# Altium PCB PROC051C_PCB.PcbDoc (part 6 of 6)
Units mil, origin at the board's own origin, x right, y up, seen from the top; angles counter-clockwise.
Board outline 3304.03 x 2647.77 mil, 6 copper layers (TOP, L2, L3, L4, L5, BOTTOM), stack 55.54 mil thick; 370 components, 273 nets, 1273 pads, 1381 vias.
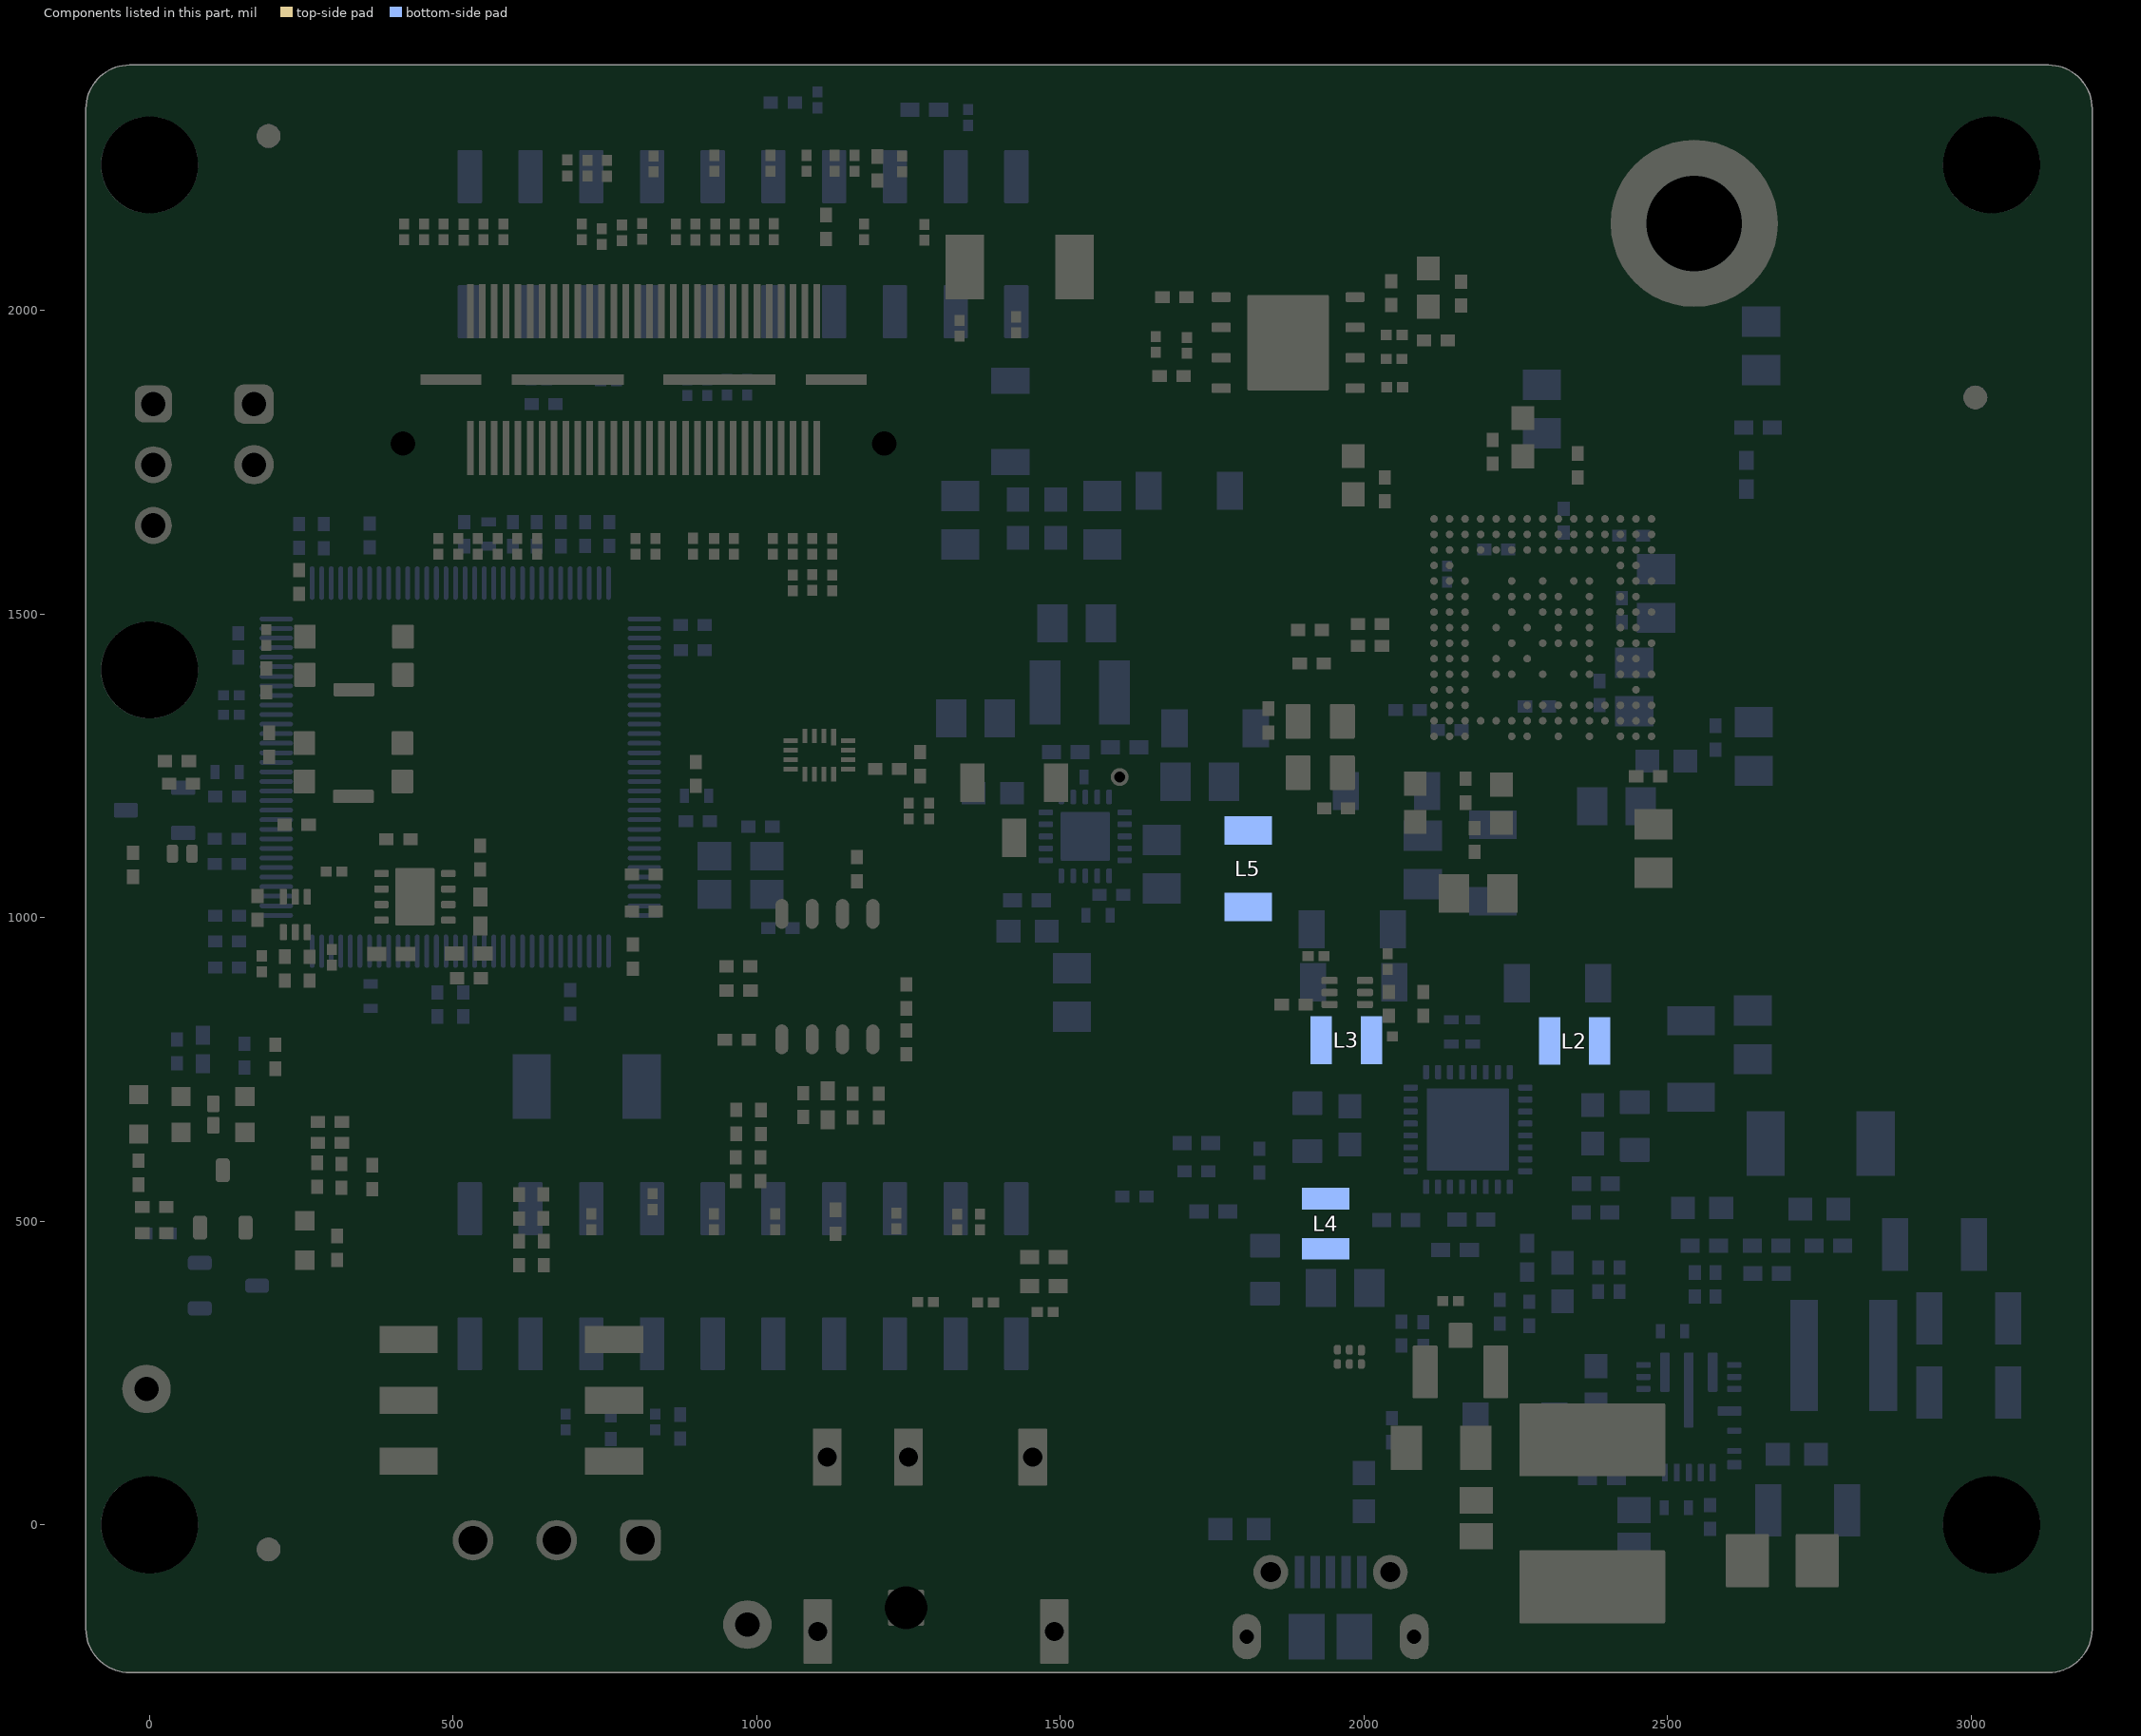
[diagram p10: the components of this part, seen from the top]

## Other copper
TOP:
  pour cut-out: 2104.44,2178.01 2104.44,2191.79 2120.19,2191.79 2143.81,2195.15 2291.6,2195.15 2315.22,2191.79 2330.97,2191.79 2330.97,2178.01 2315.22,2178.01 2291.6,2174.65 2143.81,2174.65 2120.19,2178.01
  pour cut-out: 1627.59,2266.11 1627.59,2279.89 1643.34,2279.89 1666.96,2283.25 2292.4,2283.25 2316.02,2279.89 2331.77,2279.89 2331.77,2266.11 2316.02,2266.11 2292.4,2262.75 1666.96,2262.75 1643.34,2266.11
  pour cut-out: 2361.84,1324.36 2360.61,1330.52 2357.12,1335.75 2351.89,1339.24 2345.73,1340.47 2339.57,1339.24 2334.34,1335.75 2330.85,1330.52 2329.62,1324.36 2330.85,1318.2 2334.34,1312.97 2339.57,1309.48 2345.73,1308.25 2351.89,1309.48 2357.12,1312.97 2360.61,1318.2 2361.84,1324.36
  pour cut-out: 2263.01,1622.77 2263.36,1622.51 2263.68,1622.22 2263.98,1621.9 2264.25,1621.55 2264.49,1621.19 2264.69,1620.8 2264.86,1620.4 2265,1619.99 2265.1,1619.56 2265.16,1619.13 2265.18,1618.69 2265.16,1618.26 2265.11,1617.83 2265.02,1617.4 2264.89,1616.98 2264.73,1616.58 2264.53,1616.19 2264.3,1615.82 2264.04,1615.47 2263.75,1615.15 2263.43,1614.85 2263.08,1614.58 2263.01,1614.52 2262.28,1613.97 2261.6,1613.35 2260.97,1612.68 2260.4,1611.96 2259.9,1611.19 2259.47,1610.38 2259.11,1609.54 2258.83,1608.66 2258.73,1608.31 2258.57,1607.63 2256.3,1605.36 2253.7,1607.97 2253.52,1608.61 2253.24,1609.48 2252.89,1610.33 2252.46,1611.14 2251.97,1611.92 2251.4,1612.64 2250.78,1613.32 2250.1,1613.93 2249.37,1614.49 2249.32,1614.52 2249.32,1614.53 2248.97,1614.79 2248.65,1615.08 2248.35,1615.4 2248.08,1615.74 2247.85,1616.11 2247.64,1616.49 2247.47,1616.89 2247.33,1617.31 2247.24,1617.73 2247.17,1618.16 2247.15,1618.6 2247.16,1619.04 2247.22,1619.47 2247.31,1619.9 2247.43,1620.31 2247.6,1620.72 2247.79,1621.11 2248.03,1621.48 2248.29,1621.82 2248.58,1622.15 2248.9,1622.45 2249.24,1622.72 2249.32,1622.77 2250.05,1623.32 2250.73,1623.94 2251.36,1624.61 2251.93,1625.33 2252.43,1626.1 2252.86,1626.91 2253.22,1627.75 2253.28,1627.91 2253.47,1628.44 2255.63,1630.6 2259.59,1626.65 2259.76,1626.34 2260.24,1625.56 2260.79,1624.82 2261.4,1624.14 2262.07,1623.5 2262.78,1622.93 2263.01,1622.77
  pour cut-out: 2288.6,1622.77 2288.95,1622.51 2289.27,1622.22 2289.57,1621.9 2289.84,1621.55 2290.08,1621.19 2290.28,1620.8 2290.45,1620.4 2290.59,1619.99 2290.69,1619.56 2290.75,1619.13 2290.77,1618.69 2290.75,1618.26 2290.7,1617.83 2290.61,1617.4 2290.48,1616.98 2290.32,1616.58 2290.12,1616.19 2289.89,1615.82 2289.63,1615.47 2289.34,1615.15 2289.02,1614.85 2288.67,1614.58 2288.6,1614.52 2287.87,1613.97 2287.19,1613.35 2286.56,1612.68 2285.99,1611.96 2285.49,1611.19 2285.06,1610.38 2284.7,1609.54 2284.64,1609.38 2284.45,1608.85 2282.29,1606.69 2278.33,1610.64 2278.16,1610.95 2277.68,1611.73 2277.13,1612.47 2276.52,1613.15 2275.85,1613.79 2275.14,1614.36 2274.91,1614.52 2274.91,1614.53 2274.57,1614.79 2274.24,1615.08 2273.94,1615.4 2273.67,1615.74 2273.44,1616.11 2273.23,1616.49 2273.06,1616.89 2272.92,1617.31 2272.82,1617.73 2272.76,1618.16 2272.74,1618.6 2272.75,1619.04 2272.81,1619.47 2272.9,1619.9 2273.02,1620.31 2273.19,1620.72 2273.38,1621.11 2273.62,1621.48 2273.88,1621.82 2274.17,1622.15 2274.49,1622.45 2274.83,1622.72 2274.91,1622.77 2275.64,1623.32 2276.32,1623.94 2276.95,1624.61 2277.52,1625.33 2278.02,1626.1 2278.45,1626.91 2278.81,1627.75 2278.87,1627.91 2279.06,1628.44 2281.22,1630.6 2285.18,1626.65 2285.35,1626.34 2285.83,1625.56 2286.38,1624.82 2286.99,1624.14 2287.66,1623.5 2288.37,1622.93 2288.6,1622.77
  pour cut-out: 2413.02,1324.36 2411.79,1330.52 2408.3,1335.75 2403.07,1339.24 2396.91,1340.47 2390.75,1339.24 2385.52,1335.75 2382.03,1330.52 2380.8,1324.36 2382.03,1318.2 2385.52,1312.97 2390.75,1309.48 2396.91,1308.25 2403.07,1309.48 2408.3,1312.97 2411.79,1318.2 2413.02,1324.36
  pour cut-out: 2464.2,1426.72 2462.97,1432.88 2459.48,1438.11 2454.25,1441.6 2448.09,1442.83 2441.93,1441.6 2436.7,1438.11 2433.21,1432.88 2431.98,1426.72 2433.21,1420.56 2436.7,1415.33 2441.93,1411.84 2448.09,1410.61 2454.25,1411.84 2459.48,1415.33 2462.97,1420.56 2464.2,1426.72
  pour cut-out: 2464.2,1580.26 2462.97,1586.42 2459.48,1591.65 2454.25,1595.14 2448.09,1596.37 2441.93,1595.14 2436.7,1591.65 2433.21,1586.42 2431.98,1580.26 2433.21,1574.1 2436.7,1568.87 2441.93,1565.38 2448.09,1564.15 2454.25,1565.38 2459.48,1568.87 2462.97,1574.1 2464.2,1580.26
  pour cut-out: 2464.2,1529.08 2462.97,1535.24 2459.48,1540.47 2454.25,1543.96 2448.09,1545.19 2441.93,1543.96 2436.7,1540.47 2433.21,1535.24 2431.98,1529.08 2433.21,1522.92 2436.7,1517.69 2441.93,1514.2 2448.09,1512.97 2454.25,1514.2 2459.48,1517.69 2462.97,1522.92 2464.2,1529.08
  pour cut-out: 2464.2,1477.9 2462.97,1484.06 2459.48,1489.29 2454.25,1492.78 2448.09,1494.01 2441.93,1492.78 2436.7,1489.29 2433.21,1484.06 2431.98,1477.9 2433.21,1471.74 2436.7,1466.51 2441.93,1463.02 2448.09,1461.79 2454.25,1463.02 2459.48,1466.51 2462.97,1471.74 2464.2,1477.9
  pour cut-out: 2310.66,1324.36 2309.43,1330.52 2305.94,1335.75 2300.71,1339.24 2294.55,1340.47 2288.38,1339.24 2283.16,1335.75 2279.67,1330.52 2278.44,1324.36 2279.67,1318.2 2283.16,1312.97 2288.38,1309.48 2294.55,1308.25 2300.71,1309.48 2305.94,1312.97 2309.43,1318.2 2310.66,1324.36
  pour cut-out: 2469.13,1217.07 2470.62,1218.57 2528.42,1218.57 2548.27,1198.72 2548.27,1163.16 2535.54,1150.43 2533.95,1150.43 2531.2,1147.69 2520.41,1147.69 2517.5,1144.78 2517.5,1119.4 2512.7,1114.6 2441.9,1114.6 2429.29,1127.21 2429.29,1159.14 2425.42,1163.01 2425.42,1257.43 2430.65,1262.66 2430.65,1334.75 2435.15,1339.24 2436.04,1338.35 2436.04,1261.84 2427.37,1253.17 2427.42,1253.12 2427.42,1168.45 2433.12,1162.75 2433.12,1125.29 2442.32,1116.08 2442.44,1116.2 2506.6,1116.2 2513.5,1123.1 2513.5,1147.35 2525.65,1159.5 2540.3,1159.5 2545.54,1164.75 2545.54,1199.54 2530.01,1215.07 2529.85,1214.91 2471.29,1214.91
  pour cut-out: 2457.19,1336.66 2458.22,1337.69 2462.97,1337.69 2463.66,1336.99 2463.7,1336.99 2463.7,1324.36 2463.69,1324.36 2463.69,1257.28 2470.62,1250.34 2470.62,1218.57 2469.87,1217.82 2469.13,1218.57 2469.13,1248.39 2462.45,1255.06 2462.45,1328.55 2462.8,1328.89 2456.87,1334.82 2456.87,1336.66
  text ".Layer_Name" at 269,-1200.49 h60
L2:
  pour cut-out: 3030.18,490.44 3061.24,490.44 3061.24,462.74 3030.18,462.74
  pour cut-out: 3031.1,437.37 3062.16,437.37 3062.16,409.68 3031.1,409.68
  pour cut-out: 3008.33,206.16 3039.39,206.16 3039.39,178.46 3008.33,178.46
  pour cut-out: 3006.69,257.46 3037.76,257.46 3037.76,229.76 3006.69,229.76
  pour cut-out: 3006.17,361.56 3037.24,361.56 3037.24,333.86 3006.17,333.86
  pour cut-out: 3007.25,311.5 3038.32,311.5 3038.32,283.8 3007.25,283.8
  pour cut-out: 2772.45,444.14 2803.51,444.14 2803.51,416.44 2772.45,416.44
  pour cut-out: 2706.43,415.85 2737.5,415.85 2737.5,388.15 2706.43,388.15
  pour cut-out: 2500.49,390 2531.55,390 2531.55,362.3 2500.49,362.3
  pour cut-out: 2081.85,1004.83 2112.91,1004.83 2112.91,977.13 2081.85,977.13
  pour cut-out: 1390.3,1852.05 1421.37,1852.05 1421.37,1824.36 1390.3,1824.36
  pour cut-out: 1722.37,1719.2 1753.43,1719.2 1753.43,1691.5 1722.37,1691.5
  pour cut-out: 2984.57,542.62 2980.41,538.46 2980.41,529.26 2962.64,547.03 2962.64,633.06 2911.7,684 2678.4,684 2566.8,795.6 2371.45,795.6 2254.51,912.54 2254.51,916.7 2272.3,916.7 2280.33,908.67 2378.68,810.32 2571.27,810.32 2684.16,697.44 2918.62,697.44 2976.38,639.74 2976.38,550.82
  pour cut-out: 2770.08,129.31 2801.15,129.31 2801.15,101.61 2770.08,101.61
  pour cut-out: 2782.13,-23.29 2813.2,-23.29 2813.2,-50.99 2782.13,-50.99
  pour cut-out: 2166.32,235.3 2197.39,235.3 2197.39,207.6 2166.32,207.6
  pour cut-out: 2504.2,9.5 2480.74,-13.97 2480.74,-32.6 2485.14,-37 2507.31,-37 2532.81,-11.5 2532.81,3.09 2526.62,9.29
  pour cut-out: 2561.83,211.02 2556.6,205.78 2556.6,168.03 2537.02,148.46 2537.02,138.51 2561.54,114 2572.4,114 2578.57,120.17 2578.57,204.29 2571.83,211.02
  pour cut-out: 2611.1,273 2631.8,252.3 2631.8,217.15 2638.44,210.51 2651.03,210.51 2662.88,222.37 2662.88,269.82 2640.7,292 2621.1,292 2611.1,282
  pour cut-out: 2432.48,292 2409.58,269.1 2409.58,229.37 2420.95,218 2431.06,218 2437.06,224 2437.06,254.15 2459.87,276.96 2459.87,281 2448.87,292
  pour cut-out: 2608.39,765.7 2608.39,773.21 2602.05,779.55 2577.33,779.55 2577.33,751.85 2608.39,751.85
  pour cut-out: 2252.99,862.46 2260.49,854.96 2260.49,843.23 2260.49,786.62 2234.89,761.02 2219.89,761.02 2211.54,769.37 2211.54,837.26 2236.75,862.46
  pour cut-out: 1929.95,651.49 1961.02,651.49 1961.02,623.79 1929.95,623.79
  pour cut-out: 1845,644.71 1882.53,644.71 1882.53,586.26 1845,586.26
  pour cut-out: 2330.57,349 2361.63,349 2361.63,321.3 2330.57,321.3
  pour cut-out: 2480.5,653.69 2511.56,653.69 2511.56,594 2480.5,594
  pour cut-out: 2426.3,576.1 2457.36,576.1 2457.36,548.4 2426.3,548.4
  pour cut-out: 2226.53,429.86 2257.59,429.86 2257.59,402.16 2226.53,402.16
  pour cut-out: 2183.93,491.85 2214.99,491.85 2214.99,464.15 2183.93,464.15
  pour cut-out: 1870.18,404.82 1901.25,404.82 1901.25,377.12 1870.18,377.12
  pour cut-out: 1774.72,394.7 1805.78,394.7 1805.78,367 1774.72,367
  pour cut-out: 2013.93,486.46 2045,486.46 2045,458.76 2013.93,458.76
  pour cut-out: 2053.96,857.95 2053.96,788.26 2084.5,757.72 2112.96,757.72 2116.35,761.11 2116.35,784.34 2091.55,809.14 2091.55,854.3 2083.98,861.87 2058.65,861.87 2054.78,858
  pour cut-out: 2021.46,622 2021.46,587.5 2030.66,578.3 2060.62,578.3 2060.62,624.9 2051.97,633.55
  pour cut-out: 2353.89,590.82 2310,590.82 2310,655.54 2351,655.54 2353.89,652.65
  pour cut-out: 2248.04,576.8 2159.95,576.8 2096.82,639.92 2096.82,724.19 2096.36,724.65 2247.96,724.65
  pour cut-out: 1619.7,1415.98 1619.7,1339.65 1620.12,1339.23 1669.54,1339.23 1693.51,1363.19 1693.51,1416
  pour cut-out: 1590.36,1016.8 1621.43,1016.8 1621.43,989.1 1590.36,989.1
  pour cut-out: 1379.49,1041.47 1399.91,1041.47 1404.54,1036.84 1404.54,1022.57 1391.17,1009.2 1391.17,983.99 1387.68,980.5 1364.78,980.5 1363,982.28 1363,1000.84 1370.4,1008.24 1370.4,1032.39
  pour cut-out: 1732.63,1094.38 1698.74,1094.38 1698.74,1153.21 1678.27,1173.67 1678.27,1195.37 1712.61,1195.37 1732.63,1175.35
  pour cut-out: 1585.6,1092.6 1585.79,1175.25 1497.75,1175.44 1497.75,1092.6
  pour cut-out: 2035.1,1357.4 2073.54,1357.4 2073.54,1353.76 2071,1351.22 2033.78,1351.22 2002.5,1382.5 1819.73,1382.5 1810,1372.77 1810,1237.5 1862.5,1185 1890,1185 1900,1195 1925,1195 1945,1175 1945,1152.5 1950,1147.5 1975,1147.5 2007.5,1180 2007.5,1260 2045,1297.5 2050,1297.5 2051.25,1296.25 2012.5,1257.5 2012.5,1177.5 1976.6,1141.6 1948.3,1141.6 1947.45,1142.45 1947.45,1142.55 1940,1150 1940,1172.5 1922.5,1190 1902.5,1190 1892.5,1180 1834,1180 1808.5,1205.5 1808.5,1216.6 1798.7,1226.4 1788.9,1226.4 1783.4,1231.9 1783.4,1244.8 1787.4,1248.8 1797,1250.5 1799.4,1250.8 1799.2,1251 1798,1255 1798,1374.2 1811.3,1387.5 2005,1387.5
  pour cut-out: 2353.76,1324.36 2353.15,1327.43 2351.41,1330.04 2348.8,1331.78 2345.73,1332.39 2342.66,1331.78 2340.05,1330.04 2338.31,1327.43 2337.7,1324.36 2338.31,1321.29 2340.05,1318.68 2342.66,1316.94 2345.73,1316.33 2348.8,1316.94 2351.41,1318.68 2353.15,1321.29 2353.76,1324.36
  pour cut-out: 2404.94,1324.36 2404.33,1327.43 2402.59,1330.04 2399.98,1331.78 2396.91,1332.39 2393.84,1331.78 2391.23,1330.04 2389.49,1327.43 2388.88,1324.36 2389.49,1321.29 2391.23,1318.68 2393.84,1316.94 2396.91,1316.33 2399.98,1316.94 2402.59,1318.68 2404.33,1321.29 2404.94,1324.36
  pour cut-out: 2456.12,1426.72 2455.51,1429.79 2453.77,1432.4 2451.16,1434.14 2448.09,1434.75 2445.02,1434.14 2442.41,1432.4 2440.67,1429.79 2440.06,1426.72 2440.67,1423.65 2442.41,1421.04 2445.02,1419.3 2448.09,1418.69 2451.16,1419.3 2453.77,1421.04 2455.51,1423.65 2456.12,1426.72
  pour cut-out: 2456.12,1477.9 2455.51,1480.97 2453.77,1483.58 2451.16,1485.32 2448.09,1485.93 2445.02,1485.32 2442.41,1483.58 2440.67,1480.97 2440.06,1477.9 2440.67,1474.83 2442.41,1472.22 2445.02,1470.48 2448.09,1469.87 2451.16,1470.48 2453.77,1472.22 2455.51,1474.83 2456.12,1477.9
  pour cut-out: 2456.12,1529.08 2455.51,1532.15 2453.77,1534.76 2451.16,1536.5 2448.09,1537.11 2445.02,1536.5 2442.41,1534.76 2440.67,1532.15 2440.06,1529.08 2440.67,1526.01 2442.41,1523.4 2445.02,1521.66 2448.09,1521.05 2451.16,1521.66 2453.77,1523.4 2455.51,1526.01 2456.12,1529.08
  pour cut-out: 2456.12,1580.26 2455.51,1583.33 2453.77,1585.94 2451.16,1587.68 2448.09,1588.29 2445.02,1587.68 2442.41,1585.94 2440.67,1583.33 2440.06,1580.26 2440.67,1577.19 2442.41,1574.58 2445.02,1572.84 2448.09,1572.23 2451.16,1572.84 2453.77,1574.58 2455.51,1577.19 2456.12,1580.26
  pour cut-out: 2302.58,1324.36 2301.97,1327.43 2300.23,1330.04 2297.62,1331.78 2294.55,1332.39 2291.48,1331.78 2288.87,1330.04 2287.13,1327.43 2286.52,1324.36 2287.13,1321.29 2288.87,1318.68 2291.48,1316.94 2294.55,1316.33 2297.62,1316.94 2300.23,1318.68 2301.97,1321.29 2302.58,1324.36
  pour cut-out: 295.74,1515.9 308.6,1515.9 308.6,1500.59 304.8,1496.79 304.07,1497.52 294.58,1497.52 294.58,1514.74
  pour cut-out: 1365.83,1598.26 1396.89,1598.26 1396.89,1570.56 1365.83,1570.56
  pour cut-out: 1551.63,860.61 1582.69,860.61 1582.69,832.91 1551.63,832.91
  pour cut-out: 1614.16,1262.99 1645.22,1262.99 1645.22,1235.29 1614.16,1235.29
  pour cut-out: 1304.44,1222.09 1335.51,1222.09 1335.51,1194.39 1304.44,1194.39
  pour cut-out: 1318.13,1285.85 1349.19,1285.85 1349.19,1258.15 1318.13,1258.15
  pour cut-out: 1607.15,1617.38 1638.21,1617.38 1638.21,1589.68 1607.15,1589.68
  pour cut-out: 1330.94,1412.21 1362.01,1412.21 1362.01,1384.51 1330.94,1384.51
  pour cut-out: 1551.64,1558.7 1551.64,1529.4 1611.68,1529.4 1611.68,1558.72
  pour cut-out: 1961.89,606.38 1992.96,606.38 1992.96,578.68 1961.89,578.68
  pour cut-out: 1934.82,1155.17 1943.72,1146.28 1943.72,1124.7 1941.14,1122.11 1890.45,1122.11 1872,1140.56 1872,1147.83 1879.34,1155.17
  pour cut-out: 2031.45,1052.5 2062.51,1052.5 2062.51,1024.8 2031.45,1024.8
  pour cut-out: 2343.32,1807.23 2374.38,1807.23 2374.38,1779.53 2343.32,1779.53
  text ".Layer_Name" at 265.96,-1198.29 h60
L3:
  drawing of 63 lines, arcs and shapes, not listed
  text ".Layer_Name" at 266.3,-1199.15 h60
L4:
  text ".Layer_Name" at 270.35,-1203.19 h60
L5:
  pour cut-out: 295.74,1515.9 308.6,1515.9 308.6,1500.59 304.8,1496.79 304.07,1497.52 294.58,1497.52 294.58,1514.74
  text ".Layer_Name" at 265.96,-1201.5 h60
BOTTOM:
  pour cut-out: 2169.09,-42.86 2200.15,-42.86 2200.15,-70.56 2169.09,-70.56
  text ".Layer_Name" at 269,-1200.49 h60

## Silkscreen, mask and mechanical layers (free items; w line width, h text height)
Top Overlay:
  lines w6: 1944.01,252.57 1944.01,304.68 2000.32,304.68 2008.7,296.3 2008.7,252.57 1944.01,252.57
  lines w10: 56,1744 73.53,1726.47 90.78,1709.22 90.78,1631.82 84.96,1637.64 97.42,1637.64 91.6,1631.82 ; 117,629 118,629 133,614 145,614 ; 259.69,1058.63 ccw(c266.87,1055.3) 259.69,1058.63 ; 359.73,1070.26 ccw(c366.91,1066.94) 359.73,1070.26 ; 827.2,103.68 ccw(c834.38,100.36) 827.2,103.68 ; 1098.62,2058.28 ccw(c1105.8,2054.96) 1098.62,2058.28 ; 1126.81,1323.46 ccw(c1133.99,1320.13) 1126.81,1323.46 ; 1191.31,1043.36 ccw(c1198.49,1040.04) 1191.31,1043.36 ; 1731,2042.5 ccw(c1738.18,2039.17) 1731,2042.5
  lines w25: 1280,1667.5 1280,2079.5 ; 1683.5,655.5 1986,655.5
  lines w30: 1276,742 1276,655.5 1357.1,655.5 ; 1276,932 1276,1112 ; 1598,2095.5 2044,2095.5 ; 2166,2095.5 2372,2095.5 ; 2668,1805.5 2668,2019.5
  text "1" at 1168,2055 h30 r90
  text "59" at 471,2041 h30 r90
  text "HD_CONN" at 302,1910 h30 r90
  text "VPP_1P7" at 278,1714 h30 r90
  text "2" at 1167,1706 h30 r90
  text "60" at 476,1681 h30 r90
  text "GND" at 106,1531 h30 r90
  text "1843-EVM" at 1345,1523 h30
  text "PROC051" at 1291,1458 h30
  text "REV C" at 1502,1456 h30
  text "GPIO1" at 548,1388 h30 r90
  text "SPI" at 1510,1277 h30 r90
  text "CAN" at 1368,1275 h30 r90
  text "NRST" at 548,1203 h30 r90
  text "GPIO_2" at -2,755.84 h30 r90
  text "WRM_RST" at 66,751 h30 r90
  text "NERR" at 171,749 h30 r90
  text "PWR" at 121,748 h30 r90
  text "NRST" at 256.76,548 h30 r90
  text "ON" at 509,403 h30 r90
  text "OFF" at 709,402 h30 r90
  text "SOP0" at 243,290 h30
  text "SOP1" at 249,190 h30
  text "5V_IN" at 1130,173 h30 r90
  text "SOP2" at 242,93 h30
  text "USB" at 1958,-107 h30 r90
  text "GND" at 702,-148 h30 r90
  text "CAN_L" at 541,-209 h30 r90
  text "CAN_H" at 819,-209 h30 r90
  text ".Layer_Name" at 269,-1200.49 h60
Bottom Overlay:
  drawing of 5487 lines, arcs and shapes, not listed
  text "GND" at 545,2389 h35 r90
  text "20" at 1517,2269 h30 r90
  text "2" at 465,2248 h30 r90
  text "19" at 1522,2037 h30 r90
  text "1" at 466,1986 h30 r90
  text "P1" at 14,1946 h30 r90
  text "P7" at 262,1899 h30 r90
  text "WD_ENABLE" at 1778,670 h30
  text "GND" at 640,644 h25 r90
  text "20" at 1522,552 h30 r90
  text "2" at 454,502 h30 r90
  text "WD_DISABLE" at 1793,448 h30
  text "1" at 457,339 h30 r90
  text "19" at 1520,330 h30 r90
  text "GND" at 654,207 h30 r90
  text "5V_IN" at 1551,194 h30 r90
  text "CAN_H" at 931,98 h30 r90
  text "CAN_L" at 439,94 h30 r90
  text ".Layer_Name" at 269,-1200.49 h60
Top Paste:
  text ".Layer_Name" at 269,-1200.49 h60
Bottom Paste:
  text ".Layer_Name" at 269,-1200.49 h60
Top Solder:
  text ".Layer_Name" at 269,-1200.49 h60
  text ".Layer_Name" at 269,-1200.49 h60
Bottom Solder:
  text ".Layer_Name" at 269,-1200.49 h60
Drill Guide:
  text ".Layer_Name" at 269,-1200.49 h60
M1 Board Outline:
  lines w4: -102.75,-171.24 ccw(c-32.75,-171.24) -32.75,-241.24 3127.25,-241.24 ccw(c3127.25,-171.24) 3197.25,-171.24 ; -102.75,-171 -102.75,2331.5 ; -102.75,2332.5 cw(c-32.75,2332.5) -32.75,2402.5 3127.25,2402.5 cw(c3127.25,2332.5) 3197.25,2332.5 3197.25,-172
  text ".Layer_Name" at 270.78,-1200.89 h60
M2 Board Dimensions:
  rectangle: -183,-742 192,-617
  rectangle: -308,-617 -183,-492
  lines w7: -308,-617 692,-617 ; -183,-742 -183,-492 ; -58,-742 -58,-492 ; 192,-742 192,-492 ; 442,-742 442,-492 ; -308,-742 -308,-492 692,-492 692,-742 -308,-742
  text ".Layer_Name" at 268.79,-1200.89 h60
M3 3D STEP Top:
  text ".Layer_Name" at 269,-1200.49 h60
M4 3D STEP Bottom:
  lines w6: 711,2169 705,2169 ; 1282,2245 1333,2245 1374,2204 1731,2204 1763,2236 1763,2317 1709,2371 1327,2371 1282,2326 1282,2227 1246,2191 1062,2191 1048,2177 1048,2169 ; 705,2169 1048,2169 ; 705,2169 693,2157 693,2093 703,2083 1043,2083 1054,2094 1054,2163 1048,2169
  text ".Layer_Name" at 269,-1200.49 h60
M5 Assembly Top:
  lines w10: -600,-1272.17 6000,-1272.17 ; -600,-1068.83 6002,-1068.83 ; -600,-865.5 -600,-1475.5 3405,-1475.5 6002,-1475.5 6002,-865.5 -599.5,-865.5 -599.5,-1475.5 976,-1475.5 ; 1865,-1475.5 1865,-865.5 ; 3132,-1068.83 3132,-865.5 ; 3972,-1068.83 3972,-865.5 ; 4594,-1482 4594,-1279.17
  text "COMPONENTS MARKED 'DNP' SHOULD NOT BE POPULATED." at 845.5,-660.5 h60
  text "ASSEMBLY VARIANT:" at 845,-776 h60
  text ".VariantName" at 1881,-776 h60
  text "PCB VIEWED FROM TOP SIDE" at -536.5,-997.67 h60
  text "BOARD #:" at 1940,-997.67 h60
  text ".PRJ_Number" at 2485.5,-997.67 h60
  text "REV:" at 3330,-997.67 h60
  text ".PCB_Rev" at 3621.5,-997.67 h60
  text "SVN REV:" at 4168,-997.67 h60
  text ".VersionControl_RevNumber" at 4674,-997.67 h60
  text ".Layer_Name" at 269,-1200.49 h60
  text "TID #:" at 1940,-1201 h60
  text ".TID" at 2485.5,-1201 h60
  text "LAYER NAME =" at -525.56,-1204.81 h60
  text "PLOT NAME =" at -536.5,-1406.34 h60
  text ".plot_File_Name" at 269,-1406.34 h60
  text "GENERATED    :" at 1942,-1406.34 h60
  text ".Print_Date" at 2811.5,-1406.34 h60
  text ".Print_Time" at 3540.5,-1406.34 h60
  text "TEXAS INSTRUMENTS" at 4805,-1406.34 h60
M6 Assembly Bottom:
  lines w10: -600.5,-1069.33 6001.5,-1069.33 ; -598.5,-1272.67 6001.5,-1272.67 ; 807.5,-1482.5 807.5,-1279.67 ; 1429.5,-1069.33 1429.5,-866 ; 2269.5,-1069.33 2269.5,-866 ; 3536.5,-1476 3536.5,-866 ; 4425.5,-1476 6001,-1476 6001,-866 -600.5,-866 -600.5,-1476 1996.5,-1476 6001.5,-1476 6001.5,-866
  text "COMPONENTS MARKED 'DNP' SHOULD NOT BE POPULATED." at 5794,-660 h60
  text ".VariantName" at 4750,-776 h60
  text "ASSEMBLY VARIANT:" at 5789,-776 h60
  text ".VersionControl_RevNumber" at 727.5,-998.17 h60
  text "SVN REV:" at 1233.5,-998.17 h60
  text ".PCB_Rev" at 1780,-998.17 h60
  text "REV:" at 2071.5,-998.17 h60
  text ".PRJ_Number" at 2916,-998.17 h60
  text "BOARD #:" at 3461.5,-998.17 h60
  text "PCB VIEWED FROM BOTTOM SIDE" at 5938,-998.17 h60
  text ".TID" at 2916,-1201.5 h60
  text "TID #:" at 3461.5,-1201.5 h60
  text "LAYER NAME =" at 5938.09,-1203.59 h60
  text ".Layer_Name" at 5191.24,-1206.1 h60
  text "TEXAS INSTRUMENTS" at 596.5,-1406.84 h60
  text ".Print_Time" at 1861,-1406.84 h60
  text ".Print_Date" at 2590,-1406.84 h60
  text "GENERATED    :" at 3459.5,-1406.84 h60
  text ".plot_File_Name" at 5132.5,-1406.84 h60
  text "PLOT NAME =" at 5938,-1406.84 h60
M9 Title Sheet:
  drawing of 57 lines, arcs and shapes, not listed
  text "1" at 431.84,7694.5 h70
  text "2" at 2927.5,7694.5 h70
  text "3" at 5416.84,7694.5 h70
  text "4" at 7923.51,7694.5 h70
  text "5" at 10422.5,7694.5 h70
  text "6" at 12927.5,7694.5 h70
  text "A" at -724.5,6551.5 h70
  text "A" at 14075.5,6551.5 h70
  text "B" at -724.5,4171.5 h70
  text "B" at 14075.5,4171.5 h70
  text "C" at -724.5,1796.5 h70
  text "C" at 14075.5,1796.5 h70
  text "PROJECT TITLE:" at 11035.5,-64.5 h45
  text ".PRJ_Title" at 11085.5,-197.83 h70
  text "DESIGNED FOR:" at 11035.5,-365.5 h45
  text ".PRJ_Customer" at 11085.5,-505.5 h70
  text "D" at -724.5,-573.5 h70
  text "D" at 14075.5,-573.5 h70
  text "FILE NAME:" at 11035.5,-665.5 h45
  text ".PCB_File_Name_No_Path" at 11085.5,-785.5 h70
  text "Texas Instruments (TI) and/or its licensors do not warrant the accuracy or completeness of this specification" at 6066,-947.34 h45
  text "ENGINEER:" at 11035.5,-955.5 h45
  text "LAYOUT BY:" at 12540.5,-955.5 h45
  text "or any information contained therein. TI and/or its licensors do not warrant that this design will meet" at 6021.01,-1060 h45
  text ".PRJ_Engineer" at 11085.5,-1110.49 h70
  text ".PCB_Layout" at 12591,-1110.49 h70
  text "the specifications, will be suitable for your application or fit for any particular purpose, or will operate in" at 6021.01,-1172.67 h45
  text ".Layer_Name" at 270,-1201.17 h60
  text "ALTIUM DESIGNER VERSION:" at 12540.5,-1265.5 h45
  text "an implementation. TI and/or its licensors do not warrant that the design is production worthy. You should" at 6021.01,-1285.33 h45
  text "completely validate and test your design implementation to confirm the system functionality for your application." at 6066,-1398 h45
  text ".print_Scale" at 11085.5,-1398.83 h70
  text ".Application_BuildNumber" at 12591,-1398.83 h70
  text "1" at 431.84,-1605.5 h70
  text "2" at 2927.5,-1605.5 h70
  text "3" at 5416.84,-1605.5 h70
  text "4" at 7923.51,-1605.5 h70
  text "5" at 10422.5,-1605.5 h70
  text "6" at 12927.5,-1605.5 h70
M10 Fab Notes:
  drawing of 189 lines, arcs and shapes, not listed
  text "DESIGN INFORMATION" at 12074.02,6014.17 h60
  text "MIN. TRACK WIDTH:" at 11429.46,5882.05 h60
  text "MIL" at 12680.46,5882.05 h60
  text "4" at 12497.65,5875.46 h60
  text "MIN. CLEARANCE:" at 11429.46,5757.92 h60
  text "MIL" at 12680.46,5757.92 h60
  text "3" at 12500.45,5756.91 h60
  text "MIN. VIA PAD SIZE:" at 11429.46,5633.8 h60
  text "12.6" at 12418.45,5630.91 h60
  text "MIL" at 12711.42,5628.39 h60
  text "0.05mm (2MIL)" at 12124.46,5503.9 h60
  text "MINIMUM ANNULAR RING" at 11100.23,5495.67 h60
  text "EXTERNAL" at 12832.46,5495.67 h60
  text "PER" at 11300.23,5385.55 h60
  text "IPC-D-275 CLASS 2 LEVEL C" at 11520.23,5385.54 h60
  text "MIL, HOLES" at 13008.46,5285.07 h60
  text "+/-" at 12616,5276.48 h60
  text "+/-" at 13470,5276.48 h60
  text "REGISTRATION TOLERANCES:" at 11100.23,5275.42 h60
  text "METAL" at 12300,5275.42 h60
  text "2" at 12876.2,5275.42 h60
  text "3" at 13709.2,5275.42 h60
  text "MIL" at 13825.46,5275.42 h60
  text "HOLE SIZE TOLERANCE (UNLESS OTHERWISE SPECIFIED):" at 11100.23,5177.1 h60
  text "+/-" at 13470,5174.23 h60
  text "3" at 13709.2,5173.17 h60
  text "MIL" at 13825.46,5173.17 h60
  text "MATERIAL:" at 11025.46,5035.52 h60
  text "FR-4 High Tg" at 12011.9,4907 h60
  text "X" at 12756.42,4898.55 h60
  text "FR-408" at 11446.46,4894.49 h60
  text "OTHER" at 12934.46,4894.49 h60
  text "REFER STACKUP" at 13277.53,4884.65 h60
  text "56.214 MIL(1.42mm) +/-10%" at 11766.56,4751.46 h55
  text "X" at 12936.04,4749.1 h60
  text "57.14 MIL +/-10%" at 13329.52,4748.23 h50
  text "THICKNESS:" at 11100.23,4743.24 h60
  text "OTHER" at 13051.46,4743.24 h60
  text "TOLERANCE:" at 11100.23,4604.92 h60
  text "X" at 11948.46,4604.92 h60
  text "ANSI IPC-6012 TYPE 3 CLASS 2" at 12126.48,4604.92 h60
  text "OTHER +/-" at 12126.46,4460.73 h60
  text "BOW & TWIST:" at 11100.23,4315.54 h60
  text "X" at 11948.46,4315.54 h60
  text "ANSI IPC-6012 TYPE 3 CLASS 2" at 12126.48,4315.54 h60
  text "OTHER +/-" at 12126.46,4168.85 h60
  text "DRILLING:" at 11025.46,4038.23 h60
  text "NC_DRILL FILES" at 12786.46,3933.04 h60
  text "REFERENCE:" at 11100.23,3929.1 h60
  text "X" at 11757.46,3929.01 h60
  text "AS SHOWN" at 11935.46,3929.1 h60
  text "X" at 12658.46,3929.1 h60
  text "OTHER" at 13084.46,3786.85 h60
  text "PTH COPPER THICKNESS:" at 11099.91,3783.32 h60
  text "X" at 12239.14,3783.32 h60
  text "20-30 um" at 12367.14,3783.32 h60
  text "BOARD FINISH:" at 11025.46,3635.73 h60
  text "SILKSCREEN:" at 11180.68,3525.6 h60
  text "X" at 12138.46,3525.6 h60
  text "TOP" at 12255.46,3525.6 h60
  text "X" at 12648.46,3525.6 h60
  text "BOTTOM" at 12766.46,3525.6 h60
  text "SILKSCREEN COLOR:" at 11180.68,3370.41 h60
  text "X" at 12137.46,3370.41 h60
  text "WHITE" at 12255.46,3370.41 h60
  text "OTHER" at 12766.46,3370.41 h60
  text "X" at 12850.6,3228.22 h60
  text "GREEN" at 12386.46,3226.96 h60
  text "OTHER" at 13004.46,3226.96 h60
  text "RED" at 13528.15,3225.88 h60
  text "SOLDER RESIST COLOR:" at 11180.68,3220.1 h60
  text "X" at 12268.46,3072.71 h60
  text "MATTE" at 12386.46,3072.71 h60
  text "SEMI-GLOSS" at 13004,3072.07 h60
  text "IMMERSION GOLD (ENIG)" at 12086.46,2899.94 h60
  text "ENEPIG" at 13424,2892.72 h60
  text "SURFACE FINISH:" at 11025.46,2891.72 h60
  text "IMMERSION SILVER" at 13125.67,2754.86 h60
  text "IMM. TIN/SILVER OR EQUIV" at 11355,2754.4 h60
  text "OTHER" at 12786.46,2750.47 h60
  text "X" at 12603.67,2746.86 h60
  text "NOTES: UNLESS OTHERWISE SPECIFIED." at 4751.98,2687.86 h60
  text "ARRAY/PANEL:" at 11025.46,2595.09 h60
  text "X" at 11906.1,2586.66 h60
  text "CUT AND TRIM PER M1 BOARD OUTLINE" at 12086.46,2586.87 h60
  text "N.C. ROUTE" at 12086.46,2450.9 h60
  text "V. SCORE" at 12952.46,2450.9 h60
  text "1. FOR BOARD THICKNESS AND IMPEDANCE DETAILS REFER STACKUP DOCUMENT." at 4751.98,2425.86 h60
  text "CERTIFICATION:" at 11025.46,2321.77 h60
  text "MATERIALS AND WORKMANSHIP FOR ALL PCBS" at 11750.46,2321.77 h60
  text "2. ALL VIAS ON PAD INCLUDING BGA AREA SHOULD BE FILLED WITH NON CONDUCTIVE EPOXY AND SURFACE SHOULD BE FLAT" at 4741.5,2320.42 h60
  text "TO MEET OR EXCEED THE REQUIREMENTS OF:" at 11750.46,2227.71 h60
  text "THERE ARE MANY VIAS ON THE PCB WHICH ARE EITHER ON THE PADS OR CLOSE TO PADS" at 4860.28,2213.13 h60
  text "THESE NEED TO BE FILLED WITH A NON-CONDUCTIVE EPOXY TO ENSURE FLAT SURFACE." at 4860.28,2112.39 h60
  text "X" at 11387.97,2099.08 h60
  text "ANSI IPC-A-600F CLASS ->" at 11515.96,2099.08 h60
  text "X" at 13163.97,2099.08 h60
  text "2" at 13273.96,2099.08 h60
  text "1" at 12958.96,2097.58 h60
  text "3" at 13627.96,2097.58 h60
  text "BGA AREA VIAS SHOULD BE CAPPED WITH COPPER PLATING TO ENSURE FLAT SURFACE" at 4865.78,2010.86 h60
  text "RoHS" at 12327.96,1951.39 h60
  text "OTHER" at 12972.36,1951.39 h60
  text "PER ORDER" at 13369.42,1951.39 h60
  text "FLATNESS TOLERANCE FOR VIA ON PADS: +0.000 /- 0.001 INCHES ON BOTH SIDES." at 4865.78,1902.77 h60
  text "ALL BOARDS MUST MEET OR EXCEED UL94-V0 REQUIREMENTS." at 11053,1797.57 h60
  text "3. SOLDER MASK OPENING IS KEPT SAME SIZE AS PAD (1:1)" at 4739.9,1789.33 h60
  text "THE MANUFACTURER IS REQUESTED TO RESIZE IT AS PER THEIR SOLDERMASK TOLERANCE EXCEPT NPTH DRILL AND FIDUCIALS." at 4904.94,1687.68 h60
  text "PCB MUST BEAR THE UL94V-0 UL REGISTERED MATERIAL ID NUMBER" at 11053,1681.5 h60
  text "4. VENDOR SHOULD FOLLOW ROHS COMPLIANT PROCESS AND Pb FREE FOR MANUFACTURING" at 4747.64,1564.84 h60
  text "ADDITIONAL REQUIREMENTS:" at 11025.46,1512.08 h60
  text "5. MANUFACTURER'S IDENTIFICATION,DATECODE LETTER SHALL BE SILKSCREENED ON SOLDER SIDE" at 4748.29,1437.55 h60
  text "MICROSECTION:" at 11100.23,1404.95 h60
  text "YES" at 12005.96,1404.95 h60
  text "OF THE BOARD." at 4918.29,1324.55 h60
  text "REQUIRED" at 12867.46,1260.62 h60
  text "BARE BOARD ELEC. TEST:" at 11100.23,1257.76 h60
  text "NONE" at 12405.96,1257.76 h60
  text "X" at 12749.46,1257.76 h60
  text "PER ORDER" at 13459.46,1257.76 h60
  text "6. TRACE WIDTH SHOULD BE ACCURATELY ETCHED. MAX TOLERANCE +/- 1 MIL" at 4748.29,1210.55 h60
  text "7. BOARD DIMENSIONS ARE IN (INCHES)." at 4748.29,1071.55 h60
  text "XX MIL VIAS REQUIRE NON-CONDUCTIVE FILL AND PLANARIZE" at 11268.38,1052.82 h59
  text "XX MIL VIAS REQUIRE CONDUCTIVE FILL AND PLANARIZE" at 11276.38,948.84 h60
  text "8. BOW AND TWIST SHALL NOT EXCEED 0.7% OF LONGEST SIDE" at 4748.29,929.55 h60
  text "9. LAYER TO LAYER REGISTRATION SHALL BE WITHIN +/-2 MIL" at 4748.98,813.84 h60
  text "OUTER XX MIL TRACES REQUIRE 50 OHM SINGLE-ENDED IMPEDANCE" at 11275.39,785.46 h55
  text "10. FOR ANTENNA ETCHING TOLERANCE REFER \"ANTENNA ETCHING REQUIREMENTS\" DOCUMENT." at 4705.37,694.61 h60
  text "LAYER 2 & 3 (INNER LAYERS) XX MIL WIDE, XX MIL SPACE / TRACES REQUIRE 100 OHM DIFFERENTIAL IMPEDANCE" at 11267.39,549.74 h60
  text ".Layer_Name" at 270.6,-1200.89 h60
M11 Gerber Information:
  lines w10: -600,-1272.17 6000,-1272.17 ; -600,-1068.83 6002,-1068.83 ; -600,-865.5 -600,-1475.5 3405,-1475.5 6002,-1475.5 6002,-865.5 -599.5,-865.5 -599.5,-1475.5 976,-1475.5 ; 1865,-1475.5 1865,-865.5 ; 3132,-1068.83 3132,-865.5 ; 3972,-1068.83 3972,-865.5 ; 4594,-1482 4594,-1279.17
  text "ALL ARTWORK VIEWED FROM TOP SIDE" at -536.5,-997.67 h60
  text "BOARD #:" at 1940,-997.67 h60
  text ".PRJ_Number" at 2485.5,-997.67 h60
  text "REV:" at 3330,-997.67 h60
  text ".PCB_Rev" at 3621.5,-997.67 h60
  text "SVN REV:" at 4168,-997.67 h60
  text ".VersionControl_RevNumber" at 4674,-997.67 h60
  text "LAYER NAME =" at -536.5,-1200.49 h60
  text "TID #:" at 1940,-1201 h60
  text ".TID" at 2485.5,-1201 h60
  text "PLOT NAME =" at -536.5,-1406.34 h60
  text ".plot_File_Name" at 269,-1406.34 h60
  text "GENERATED    :" at 1942,-1406.34 h60
  text ".Print_Date" at 2811.5,-1406.34 h60
  text ".Print_Time" at 3540.5,-1406.34 h60
  text "TEXAS INSTRUMENTS" at 4805,-1406.34 h60
M12 Stackup:
  drawing of 417 lines, arcs and shapes, not listed
  text "LAYER STACKUP :" at 5183.41,7377.07 h60
  text "Layer" at 5204.39,7196.49 h60
  text "Name" at 5614.31,7196.49 h60
  text "Material" at 6544.05,7196.49 h60
  text "Thickness" at 7733.71,7196.49 h60
  text "Constant" at 8383.55,7196.49 h60
  text "Board Layer Stack" at 8953.41,7196.49 h60
  text "1" at 5204.39,7076.49 h60
  text "Top Overlay" at 5614.31,7076.49 h60
  text "2" at 5204.39,6956.49 h60
  text "Top Solder" at 5614.31,6956.49 h60
  text "Solder Resist" at 6544.05,6956.49 h60
  text "0.80mil" at 7733.71,6956.49 h60
  text "3.5" at 8383.55,6956.49 h60
  text "3" at 5204.39,6836.49 h60
  text "TOP" at 5614.31,6836.49 h60
  text "Copper" at 6544.05,6836.49 h60
  text "1.60mil" at 7733.71,6836.49 h60
  text "4" at 5204.39,6716.49 h60
  text "Dielectric1" at 5614.31,6716.49 h60
  text "Rogers 4835" at 6544.05,6716.49 h60
  text "4.00mil" at 7733.71,6716.49 h60
  text "3.66" at 8383.55,6716.49 h60
  text "L1-L2" at 4858.49,6644.53 h60 r90
  text "5" at 5204.39,6596.49 h60
  text "L2" at 5614.31,6596.49 h60
  text "Copper" at 6544.05,6596.49 h60
  text "1.20mil" at 7733.71,6596.49 h60
  text "6" at 5204.39,6476.49 h60
  text "Dielectric2" at 5614.31,6476.49 h60
  text "370HR Prepreg 1080" at 6544.05,6476.49 h60
  text "5.70mil" at 7733.71,6476.49 h60
  text "3.9" at 8383.55,6476.49 h60
  text "7" at 5204.39,6356.49 h60
  text "L3" at 5614.31,6356.49 h60
  text "Copper" at 6544.05,6356.49 h60
  text "1.20mil" at 7733.71,6356.49 h60
  text "8" at 5204.39,6236.49 h60
  text "Dielectric3" at 5614.31,6236.49 h60
  text "370HR Prepreg 1080" at 6544.05,6236.49 h60
  text "28.00mil" at 7733.71,6236.49 h60
  text "4.36" at 8383.55,6236.49 h60
  text "L1-L6" at 4676.89,6155.29 h60 r90
  text "9" at 5204.39,6116.49 h60
  text "L4" at 5614.31,6116.49 h60
  text "Copper" at 6544.05,6116.49 h60
  text "1.20mil" at 7733.71,6116.49 h60
  text "10" at 5204.39,5996.49 h60
  text "Dielectric4" at 5614.31,5996.49 h60
  text "370HR Prepreg 1080" at 6544.05,5996.49 h60
  text "5.84mil" at 7733.71,5996.49 h60
  text "3.9" at 8383.55,5996.49 h60
  text "11" at 5204.39,5876.49 h60
  text "L5" at 5614.31,5876.49 h60
  text "Copper" at 6544.05,5876.49 h60
  text "1.20mil" at 7733.71,5876.49 h60
  text "12" at 5204.39,5756.49 h60
  text "Dielectric5" at 5614.31,5756.49 h60
  text "370HR Prepreg 1080" at 6544.05,5756.49 h60
  text "4.00mil" at 7733.71,5756.49 h60
  text "4.26" at 8383.55,5756.49 h60
  text "13" at 5204.39,5636.49 h60
  text "BOTTOM" at 5614.31,5636.49 h60
  text "Copper" at 6544.05,5636.49 h60
  text "1.60mil" at 7733.71,5636.49 h60
  text "14" at 5204.39,5516.49 h60
  text "Bottom Solder" at 5614.31,5516.49 h60
  text "Solder Resist" at 6544.05,5516.49 h60
  text "0.80mil" at 7733.71,5516.49 h60
  text "3.5" at 8383.55,5516.49 h60
  text "15" at 5204.39,5396.49 h60
  text "Bottom Overlay" at 5614.31,5396.49 h60
  text "IMPEDANCE TABLE :" at 5347.56,5063.25 h70
  text "LAYER NO" at 5399.74,4721.7 h70
  text "CONDUCTOR WIDTH" at 6045.26,4721.7 h70
  text "IMPEDANCE +/-10%" at 8245.23,4721.57 h70
  text "REFERENCE GND" at 9426.27,4721.57 h70
  text "DIFF. / PAIR / SPACING" at 7107.21,4661.55 h70
  text "CPWG / SPACING" at 7645.56,4655.96 h70
  text "5.2mil" at 6284.33,4501.43 h70
  text "L2-GND" at 9641.61,4499.79 h70
  text "5mil" at 7214.22,4496.4 h70
  text "N/A" at 7749.12,4496.27 h70
  text "100ohm" at 8515.32,4496.35 h70
  text "1 (TOP)" at 5469.46,4493.72 h70
  text ".Layer_Name" at 268.79,-1200.89 h60
M13 Component Bodies Top:
  text ".Layer_Name" at 269,-1200.49 h60
M14 Component Bodies Bottom:
  text ".Layer_Name" at 269,-1200.49 h60
M15 Courtyards Top:
  text ".Layer_Name" at 269,-1200.49 h60
M16 Courtyards Bottom:
  text ".Layer_Name" at 269,-1200.49 h60
Drill Drawing:
  drawing of 158 lines, arcs and shapes, not listed
  text "Symbol" at -315.76,7243.02 h50.4
  text "Count" at 41.55,7243.02 h50.4
  text "Hole Size" at 456.44,7243.02 h50.4
  text "Plated" at 1263.21,7243.02 h50.4
  text "Hole Type" at 1620.52,7243.02 h50.4
  text "Drill Layer Pair" at 2137.38,7243.02 h50.4
  text "Pad Shape" at 2973.34,7243.02 h50.4
  text "Hole Length" at 3738.12,7243.02 h50.4
  text "30" at 41.55,7138.02 h42
  text "7.87mil (0.200mm)" at 456.44,7138.02 h42
  text "PTH" at 1263.21,7138.02 h42
  text "Round" at 1620.52,7138.02 h42
  text "TOP - BOTTOM" at 2137.38,7138.02 h42
  text "Rounded" at 2973.34,7138.02 h42
  text "-" at 3738.12,7138.02 h42
  text "4" at 41.55,7033.02 h42
  text "8.00mil (0.203mm)" at 456.44,7033.02 h42
  text "PTH" at 1263.21,7033.02 h42
  text "Round" at 1620.52,7033.02 h42
  text "TOP - BOTTOM" at 2137.38,7033.02 h42
  text "Rounded" at 2973.34,7033.02 h42
  text "-" at 3738.12,7033.02 h42
  text "7" at 41.55,6928.02 h42
  text "12.10mil (0.307mm)" at 456.44,6928.02 h42
  text "PTH" at 1263.21,6928.02 h42
  text "Round" at 1620.52,6928.02 h42
  text "TOP - BOTTOM" at 2137.38,6928.02 h42
  text "Rounded" at 2973.34,6928.02 h42
  text "-" at 3738.12,6928.02 h42
  text "B" at -336.81,6920.03 h46.67
  text "811" at 41.55,6823.02 h42
  text "12.20mil (0.310mm)" at 456.44,6823.02 h42
  text "PTH" at 1263.21,6823.02 h42
  text "Round" at 1620.52,6823.02 h42
  text "TOP - BOTTOM" at 2137.38,6823.02 h42
  text "Rounded" at 2973.34,6823.02 h42
  text "-" at 3738.12,6823.02 h42
  text "1" at 41.55,6718.02 h42
  text "17.72mil (0.450mm)" at 456.44,6718.02 h42
  text "PTH" at 1263.21,6718.02 h42
  text "Round" at 1620.52,6718.02 h42
  text "TOP - BOTTOM" at 2137.38,6718.02 h42
  text "Rounded" at 2973.34,6718.02 h42
  text "-" at 3738.12,6718.02 h42
  text "2" at 41.55,6613.02 h42
  text "23.62mil (0.600mm)" at 456.44,6613.02 h42
  text "PTH" at 1263.21,6613.02 h42
  text "Slot" at 1620.52,6613.02 h42
  text "TOP - BOTTOM" at 2137.38,6613.02 h42
  text "Rounded" at 2973.34,6613.02 h42
  text "51.18mil (1.300mm)" at 3738.12,6613.02 h42
  text "D" at -336.81,6605.03 h46.67
  text "3" at 41.55,6508.02 h42
  text "31.50mil (0.800mm)" at 456.44,6508.02 h42
  text "PTH" at 1263.21,6508.02 h42
  text "Rectangle" at 1620.52,6508.02 h42
  text "TOP - BOTTOM" at 2137.38,6508.02 h42
  text "Rounded Rectangle" at 2973.34,6508.02 h42
  text "78.74mil (2.000mm)" at 3738.12,6508.02 h42
  text "2" at 41.55,6403.02 h42
  text "31.50mil (0.800mm)" at 456.44,6403.02 h42
  text "PTH" at 1263.21,6403.02 h42
  text "Rectangle" at 1620.52,6403.02 h42
  text "TOP - BOTTOM" at 2137.38,6403.02 h42
  text "Rounded Rectangle" at 2973.34,6403.02 h42
  text "90.55mil (2.300mm)" at 3738.12,6403.02 h42
  text "2" at 41.55,6298.02 h42
  text "33.47mil (0.850mm)" at 456.44,6298.02 h42
  text "PTH" at 1263.21,6298.02 h42
  text "Round" at 1620.52,6298.02 h42
  text "TOP - BOTTOM" at 2137.38,6298.02 h42
  text "Rounded" at 2973.34,6298.02 h42
  text "-" at 3738.12,6298.02 h42
  text "4" at 41.55,6193.02 h42
  text "40.00mil (1.016mm)" at 456.44,6193.02 h42
  text "PTH" at 1263.21,6193.02 h42
  text "Round" at 1620.52,6193.02 h42
  text "TOP - BOTTOM" at 2137.38,6193.02 h42
  text "(Mixed)" at 2973.34,6193.02 h42
  text "-" at 3738.12,6193.02 h42
  text "2" at 41.55,6088.02 h42
  text "40.16mil (1.020mm)" at 456.44,6088.02 h42
  text "NPTH" at 1263.21,6088.02 h42
  text "Round" at 1620.52,6088.02 h42
  text "TOP - BOTTOM" at 2137.38,6088.02 h42
  text "Rounded" at 2973.34,6088.02 h42
  text "-" at 3738.12,6088.02 h42
  text "F" at -336.81,6080.03 h46.67
  text "3" at 41.55,5983.02 h42
  text "40.16mil (1.020mm)" at 456.44,5983.02 h42
  text "PTH" at 1263.21,5983.02 h42
  text "Round" at 1620.52,5983.02 h42
  text "TOP - BOTTOM" at 2137.38,5983.02 h42
  text "(Mixed)" at 2973.34,5983.02 h42
  text "-" at 3738.12,5983.02 h42
  text "E" at -336.81,5975.03 h46.67
  text "3" at 41.55,5878.02 h42
  text "47.24mil (1.200mm)" at 456.44,5878.02 h42
  text "PTH" at 1263.21,5878.02 h42
  text "Round" at 1620.52,5878.02 h42
  text "TOP - BOTTOM" at 2137.38,5878.02 h42
  text "(Mixed)" at 2973.34,5878.02 h42
  text "-" at 3738.12,5878.02 h42
  text "1" at 41.55,5773.02 h42
  text "70.87mil (1.800mm)" at 456.44,5773.02 h42
  text "NPTH" at 1263.21,5773.02 h42
  text "Rectangle" at 1620.52,5773.02 h42
  text "TOP - BOTTOM" at 2137.38,5773.02 h42
  text "Rounded Rectangle" at 2973.34,5773.02 h42
  text "71.00mil (1.803mm)" at 3738.12,5773.02 h42
  text "1" at 41.55,5668.02 h42
  text "157.48mil (4.000mm)" at 456.44,5668.02 h42
  text "PTH" at 1263.21,5668.02 h42
  text "Round" at 1620.52,5668.02 h42
  text "TOP - BOTTOM" at 2137.38,5668.02 h42
  text "Rounded" at 2973.34,5668.02 h42
  text "-" at 3738.12,5668.02 h42
  text "5" at 41.55,5563.02 h42
  text "160.00mil (4.064mm)" at 456.44,5563.02 h42
  text "NPTH" at 1263.21,5563.02 h42
  text "Round" at 1620.52,5563.02 h42
  text "TOP - BOTTOM" at 2137.38,5563.02 h42
  text "Rounded" at 2973.34,5563.02 h42
  text "-" at 3738.12,5563.02 h42
  text "881 Total" at 41.55,5458.02 h42
  text "Slot definitions :" at -315.76,5354.54 h42
  text "Routed Path Length" at 409.92,5354.54 h42
  text "= Calculated from tool start centre position to tool end centre position." at 1184.59,5354.54 h42
  text "Hole Length" at 409.92,5282.56 h42
  text "= Routed Path Length + Tool Size = Slot length as defined in the PCB layout" at 897.68,5282.56 h42
  text "Drill Table" at 69.28,5134.97 h50
  text "FOR PTH +/- 3MIL" at 65.74,5041.08 h50
  text "FOR NPTH +/- 2MIL" at 62.65,4964.49 h50
  text "FOR 7.874MIL DRILL +0/-7.874MIL" at 55.19,4883.32 h50
  text "FOR 8MIL DRILL +0/-8MIL" at 52.41,4793.95 h50
  text "FOR 12.1MIL DRILL +0/-12.1MIL" at 50.73,4709.43 h50
  text "FOR 12.2MIL DRILL +0/-12.2MIL" at 49.06,4631.01 h50
  text "Symbol" at 68.13,4296.78 h72
  text "Count" at 350.03,4296.78 h72
  text "Hole Size" at 642.44,4296.78 h72
  text "Plated" at 1160.39,4296.78 h72
  text "Hole Type" at 1407.86,4296.78 h72
  text "Drill Layer Pair" at 1768.15,4296.78 h72
  text "Hole Length" at 2260.97,4296.78 h72
  text "Routed Path Length" at 2673.27,4296.78 h72
  text "529" at 350.03,4172.6 h60
  text "5.90mil (0.150mm)" at 642.44,4172.6 h60
  text "PTH" at 1160.39,4172.6 h60
  text "Round" at 1407.86,4172.6 h60
  text "TOP - L2" at 1768.15,4172.6 h60
  text "-" at 2260.97,4172.6 h60
  text "-" at 2673.27,4172.6 h60
  text "529 Total" at 350.03,4048.42 h60
  text "FOR 5.9MIL DRILL +0/-5.9MIL" at 135.78,3879.38 h50
  text ".Layer_Name" at 269,-1200.49 h60
M17 Embedded Cavity:
  text ".Layer_Name" at 269,-1200.49 h60
M18 Embedded Assembly:
  text ".Layer_Name" at 269,-1200.49 h60
M19 Embedded Keepout:
  text ".Layer_Name" at 269,-1200.49 h60
2:
  drawing of 231 lines, arcs and shapes, not listed

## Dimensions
-102.75,2332.5 to 3197.25,2332.5 on M2 Board Dimensions
3127.25,2402.5 to 3127.25,-241.24 on M2 Board Dimensions
-308,-742 to 692,-742 on M2 Board Dimensions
